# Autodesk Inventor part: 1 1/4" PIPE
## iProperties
Shininess: 60.0
Created: 2001-04
Part Number: 1 1/4" PIPE
Material: Steel, Mild
Document SubType Name: Modeling
Designer: Administrator
Density: 7.86
Volumn: 14.15699511414508
Area: 164.85894032490236
PropertySet Name: Model Information
Control State: 0
Master: False
Checked Out: False
Title: PIPE, 1 1/4", ONE THREADED END
Author: Administrator
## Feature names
1. Extrusion1
2. Revolution1
3. Mirror1
